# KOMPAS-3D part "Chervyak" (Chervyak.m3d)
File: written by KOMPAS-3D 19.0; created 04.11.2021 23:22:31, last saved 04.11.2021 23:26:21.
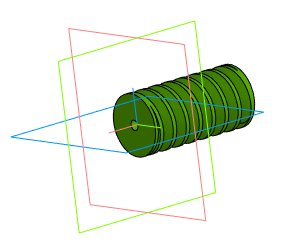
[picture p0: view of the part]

Document properties: Полное имя файла: D:\3D_print\3D проекты Компас 3D\Редуктор (Снова)\Chervyak.m3d

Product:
- Part/product: Chervyak
    Материал: АБС 0603Т ТУ 2214-019-002 03521-96 (density 0 kg/m3)
  - Body: Тело 1
      Масса: 0.0497825

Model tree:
1. ЛСК (Цилиндрический червяк):1  (with: Цилиндрический червяк:1, Плоскость XY, Плоскость ZX, Плоскость ZY, Ось X, Ось Y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)  (labels: &Фаска (Цилиндрический червяк):1)  (2 pattern instances)
     Ось X. X = 1; Ось Y. Y = 1; Ось Z. Z = 1; Высота = 43.4248; Диаметр 2 = 10
2. Впадина (Цилиндрический червяк):1
     N 1 = 1; Шаг 1 = 1; Шаг 2 = 180; Номер 1 = 1
3. Цилиндрический червяк:1
4. Эскиз:5  (with: Контур червяка (Цилиндрический червяк):1, Впадина (Цилиндрический червяк):1)
5. Элемент выдавливания:2
     Расстояние 1 = 1
6. Эскиз:6  (with: Контур червяка (Цилиндрический червяк):1, Впадина (Цилиндрический червяк):1)
7. Элемент выдавливания:3
     Расстояние 1 = 1
8. Эскиз:7  (with: Элемент выдавливания:2)
9. Элемент выдавливания:4  (labels: АБС 0603Т ТУ 2214-019-002 03521-96)
     Расстояние 2 = 36

Expressions: M_PI*VGWCylS_1_M; M_PI*VGWCylS_1_M*round(VGWCylS_1_Z1); (VGWCylS_1_B1+M_PI*VGWCylS_1_M)/(M_PI*VGWCylS_1_M*round(VGWCylS_1_Z1))+1; VGWCylS_1_Q*VGWCylS_1_M
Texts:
  SHAFT3D
  Число отображаемых витков
  Коэффициент диаметра червяка
  Длина нарезанной части червяка
  Коэффициент высоты головки витка
  Коэффициент радиального зазора у поверхности впадин червяка
  Угол профиля в осевом сечении червяка
  Коэффициент расчетной толщины витка
  Коэффициент высоты ножки витка
  round(VGWCylS_1_Z1)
